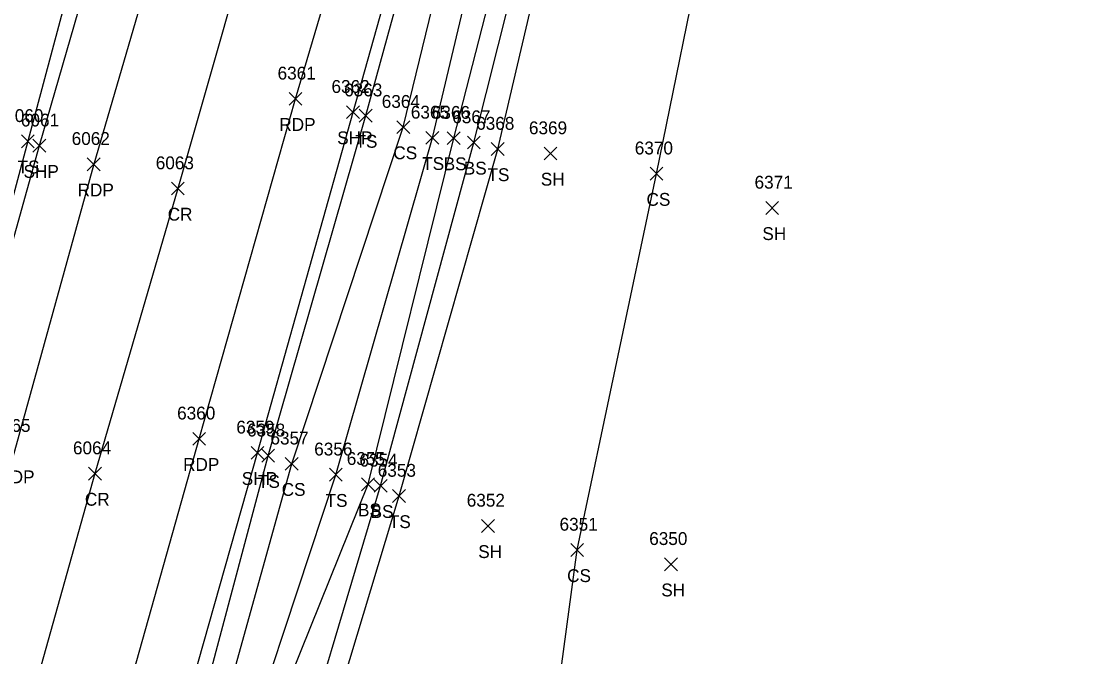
# Model space of a CAD drawing. Extents: x 1443912 to 1445411, y 621446 to 623693.
# Drawn here: x 1444530.8 to 1444695.3, y 621831 to 621930 of the extents above; entities that cross this region are included whole.
import ezdxf

# ---------------------------------------------------------------- set-up
doc = ezdxf.new("R2010")
doc.units = 0
for name, color, linetype in [('L_A', 7, 'Continuous'), ('L_I', 7, 'Continuous'), ('L_TIC', 7, 'Continuous'), ('LELB', 7, 'Continuous'), ('P_A', 7, 'Continuous'), ('P_I', 7, 'Continuous'), ('P_TIC', 7, 'Continuous'), ('PET', 7, 'Continuous'), ('PRC', 7, 'Continuous'), ('PSP', 7, 'Continuous')]:
    doc.layers.add(name, color=color, linetype=linetype)

msp = doc.modelspace()

# ---------------------------------------------------------------- linework, layer by layer
at = {"layer": 'L_TIC'}
for points in [[(1444583.53, 621914.31), (1444585.53, 621916.31)], [(1444585.53, 621914.31), (1444583.53, 621916.31)], [(1444589.39, 621912.52), (1444591.39, 621914.52)], [(1444591.39, 621912.52), (1444589.39, 621914.52)], [(1444530.89, 621910.31), (1444532.89, 621912.31)], [(1444532.89, 621910.31), (1444530.89, 621912.31)], [(1444593.92, 621910.85), (1444595.92, 621912.85)], [(1444595.92, 621910.85), (1444593.92, 621912.85)], [(1444597.24, 621910.81), (1444599.24, 621912.81)], [(1444599.24, 621910.81), (1444597.24, 621912.81)], [(1444600.37, 621910.13), (1444602.37, 621912.13)], [(1444602.37, 621910.13), (1444600.37, 621912.13)], [(1444604.09, 621909.11), (1444606.09, 621911.11)], [(1444606.09, 621909.11), (1444604.09, 621911.11)], [(1444612.32, 621908.41), (1444614.32, 621910.41)], [(1444614.32, 621908.41), (1444612.32, 621910.41)], [(1444628.84, 621905.27), (1444630.84, 621907.27)], [(1444630.84, 621905.27), (1444628.84, 621907.27)], [(1444646.85, 621899.94), (1444648.85, 621901.94)], [(1444648.85, 621899.94), (1444646.85, 621901.94)], [(1444568.34, 621861.36), (1444570.34, 621863.36)], [(1444570.34, 621861.36), (1444568.34, 621863.36)], [(1444572, 621860.11), (1444574, 621862.11)], [(1444574, 621860.11), (1444572, 621862.11)], [(1444578.87, 621858.4), (1444580.87, 621860.4)], [(1444580.87, 621858.4), (1444578.87, 621860.4)], [(1444583.89, 621856.92), (1444585.89, 621858.92)], [(1444585.89, 621856.92), (1444583.89, 621858.92)], [(1444585.86, 621856.67), (1444587.86, 621858.67)], [(1444587.86, 621856.67), (1444585.86, 621858.67)], [(1444588.72, 621855.09), (1444590.72, 621857.09)], [(1444590.72, 621855.09), (1444588.72, 621857.09)], [(1444602.58, 621850.43), (1444604.58, 621852.43)], [(1444604.58, 621850.43), (1444602.58, 621852.43)], [(1444616.47, 621846.69), (1444618.47, 621848.69)], [(1444618.47, 621846.69), (1444616.47, 621848.69)], [(1444631.1, 621844.46), (1444633.1, 621846.46)], [(1444633.1, 621844.46), (1444631.1, 621846.46)]]:
    msp.add_lwpolyline(points, dxfattribs=at)
at = {"layer": 'LELB'}
for points in [[(1444574.55, 622074.53), (1444566.78, 622059.21), (1444562.93, 622059.13), (1444561.5, 622033.21), (1444553.8, 621993.71), (1444545.42, 621962.05), (1444531.89, 621911.31), (1444519.55, 621865.32), (1444501.88, 621802.99), (1444488.02, 621753.84), (1444471.78, 621701.48), (1444460.31, 621656.88), (1444459.55, 621655.45), (1444452.09, 621632.21), (1444445.68, 621624.35), (1444438.52, 621621.89)], [(1444566.06, 621662.53), (1444540.75, 621668.47), (1444530.66, 621674.02), (1444525.23, 621679.72), (1444521.9, 621690.63), (1444527.67, 621715.46), (1444537.6, 621748.27), (1444544.57, 621771.14), (1444552.88, 621800.55), (1444569.34, 621862.36), (1444584.53, 621915.31), (1444599.33, 621969.16), (1444603.57, 621978.29), (1444612.14, 621984.45), (1444630.38, 621984.58), (1444648.65, 621983.32), (1444669.84, 621978.95)], [(1444562.11, 621788.81), (1444558.44, 621808.65), (1444573, 621861.11), (1444590.39, 621913.52), (1444603.53, 621967.44), (1444606.55, 621977.79), (1444612.68, 621980.77)], [(1444573.52, 621729.96), (1444606.82, 621757.8), (1444615.68, 621770.45), (1444599.05, 621772.87), (1444599.34, 621775.96), (1444583.66, 621779.46), (1444578.87, 621781.94), (1444577.18, 621792.61), (1444574.39, 621805.13), (1444589.72, 621856.09), (1444605.09, 621910.11), (1444615.08, 621952.69), (1444616.59, 621961.76), (1444617.15, 621962.73), (1444617.2, 621963.71), (1444617.35, 621964.73), (1444618.57, 621976.39)], [(1444596.93, 621775.31), (1444596.97, 621774.74), (1444581.99, 621775.15), (1444574.89, 621780.65), (1444572.86, 621790.77), (1444569.59, 621804.75), (1444563.93, 621805.88), (1444584.89, 621857.92), (1444598.24, 621911.81), (1444611.93, 621964.98), (1444612.45, 621975.13), (1444616.41, 621975.01)], [(1444596.93, 621775.31), (1444582.89, 621775.95), (1444576.67, 621781.14), (1444575.69, 621791.72), (1444571.4, 621805.9), (1444586.86, 621857.67), (1444601.37, 621911.13), (1444614.74, 621964.14), (1444616.41, 621975.01)], [(1444599.05, 621772.87), (1444581.28, 621773.15), (1444573.42, 621779.76), (1444571.45, 621790.67), (1444568.62, 621802.83), (1444561.95, 621805.21), (1444579.87, 621859.4), (1444594.92, 621911.85), (1444607.97, 621966.71)], [(1444615.68, 621770.45), (1444617.26, 621774.09), (1444611.19, 621801.02), (1444617.47, 621847.69), (1444629.84, 621906.27), (1444637.66, 621944.7), (1444644.37, 621956.1), (1444645.62, 621958.64)]]:
    msp.add_lwpolyline(points, dxfattribs=at)
at = {"layer": 'P_TIC'}
for points in [[(1444572.59, 621916.93), (1444574.59, 621918.93)], [(1444574.59, 621916.93), (1444572.59, 621918.93)], [(1444581.56, 621914.85), (1444583.56, 621916.85)], [(1444583.56, 621914.85), (1444581.56, 621916.85)], [(1444532.68, 621909.62), (1444534.68, 621911.62)], [(1444534.68, 621909.62), (1444532.68, 621911.62)], [(1444541.16, 621906.74), (1444543.16, 621908.74)], [(1444543.16, 621906.74), (1444541.16, 621908.74)], [(1444554.25, 621902.96), (1444556.25, 621904.96)], [(1444556.25, 621902.96), (1444554.25, 621904.96)], [(1444557.59, 621864), (1444559.59, 621866)], [(1444559.59, 621864), (1444557.59, 621866)], [(1444566.68, 621861.81), (1444568.68, 621863.81)], [(1444568.68, 621861.81), (1444566.68, 621863.81)], [(1444541.35, 621858.58), (1444543.35, 621860.58)], [(1444543.35, 621858.58), (1444541.35, 621860.58)]]:
    msp.add_lwpolyline(points, dxfattribs=at)
at = {"layer": 'PET'}
for points in [[(1444707.78, 622511.05), (1444700.03, 622482.58), (1444691.73, 622453.67), (1444679.73, 622411.23), (1444667.69, 622368.84), (1444653.08, 622317.67), (1444637.74, 622256.92), (1444626.42, 622209.58), (1444619.02, 622182.67), (1444605.37, 622130.08), (1444589.4, 622078.61), (1444578.44, 622026.86), (1444565.52, 621990.05), (1444556.87, 621958.17), (1444542.16, 621907.74), (1444529.8, 621863.07), (1444511.99, 621799.88), (1444498.16, 621751.76), (1444483.13, 621697.3), (1444470.84, 621653.16), (1444463.41, 621627.34), (1444449.07, 621575.52), (1444430.26, 621508.83), (1444421.17, 621471.46)], [(1444444.37, 621464.94), (1444461.94, 621522.87), (1444475.59, 621570.55), (1444487.99, 621616.26), (1444502.92, 621667.73), (1444516.83, 621718.16), (1444526.41, 621751.49), (1444537.28, 621789.32), (1444558.59, 621865), (1444573.59, 621917.93), (1444597.58, 621998.81), (1444610.14, 622044.19), (1444623.48, 622089.5), (1444632.2, 622118.09)]]:
    msp.add_lwpolyline(points, dxfattribs=at)
at = {"layer": 'PRC'}
msp.add_lwpolyline([(1444618.32, 622127.38), (1444604.97, 622075.74), (1444590.11, 622023.77), (1444578.57, 621985.29), (1444569.73, 621954.72), (1444555.25, 621903.96), (1444542.35, 621859.58), (1444524.46, 621796.02), (1444511.19, 621747.94), (1444495.68, 621693.61), (1444483.2, 621649.28), (1444475.93, 621623.97), (1444461.82, 621572.2), (1444443.22, 621505.41), (1444432.75, 621467.94)], dxfattribs=at)
at = {"layer": 'PSP'}
for points in [[(1444596.17, 622132.46), (1444585.6, 622096.58), (1444576.22, 622067.8), (1444567.15, 622029.85), (1444556.7, 621993.22), (1444548.18, 621960.88), (1444533.68, 621910.62), (1444520.92, 621865.12), (1444503.16, 621802.82), (1444490.06, 621753.65), (1444474.75, 621700.87), (1444461.97, 621656.27), (1444456.61, 621636.09), (1444438.52, 621570.3), (1444424.57, 621519.38), (1444411.29, 621473.11)], [(1444455.66, 621462.75), (1444472.05, 621519.48), (1444485.13, 621568.3), (1444497.88, 621612.67), (1444505.4, 621638.58), (1444519.01, 621689.59), (1444525.59, 621713.97), (1444535.94, 621748.74), (1444541.51, 621770.15), (1444550.94, 621803.78), (1444567.68, 621862.81), (1444582.56, 621915.85), (1444597.67, 621969.6), (1444608.45, 622008), (1444628.13, 622076.36), (1444639.3, 622115.36)]]:
    msp.add_lwpolyline(points, dxfattribs=at)

# ---------------------------------------------------------------- texts
at = {"layer": 'L_A'}
for s, p in [('TS', (1444582.93, 621910.31)), ('CS', (1444588.83, 621908.52)), ('TS', (1444593.33, 621906.85)), ('BS', (1444596.68, 621906.81)), ('TS', (1444530.3, 621906.31)), ('BS', (1444599.81, 621906.13)), ('TS', (1444603.5, 621905.11)), ('SH', (1444611.81, 621904.41)), ('CS', (1444628.28, 621901.27)), ('SH', (1444646.33, 621895.94)), ('TS', (1444567.75, 621857.36)), ('CS', (1444571.44, 621856.11)), ('TS', (1444578.28, 621854.4)), ('BS', (1444583.33, 621852.92)), ('BS', (1444585.3, 621852.67)), ('TS', (1444588.13, 621851.09)), ('SH', (1444602.06, 621846.43)), ('CS', (1444615.91, 621842.69)), ('SH', (1444630.58, 621840.46))]:
    msp.add_text(s, height=2, dxfattribs=at).set_placement(p)
at = {"layer": 'L_I'}
for s, p in [('6363', (1444581.17, 621918.31)), ('6364', (1444587.03, 621916.52)), ('6365', (1444591.56, 621914.85)), ('6366', (1444594.83, 621914.81)), ('6060', (1444528.37, 621914.31)), ('6367', (1444598.01, 621914.13)), ('6368', (1444601.74, 621913.11)), ('6369', (1444609.96, 621912.41)), ('6370', (1444626.45, 621909.27)), ('6371', (1444645.11, 621903.94)), ('6358', (1444566.04, 621865.36)), ('6357', (1444569.69, 621864.11)), ('6356', (1444576.51, 621862.4)), ('6355', (1444581.58, 621860.92)), ('6354', (1444583.55, 621860.67)), ('6353', (1444586.41, 621859.09)), ('6352', (1444600.27, 621854.43)), ('6351', (1444614.73, 621850.69)), ('6350', (1444628.7, 621848.46))]:
    msp.add_text(s, height=2, dxfattribs=at).set_placement(p)
at = {"layer": 'P_A'}
for s, p in [('RDP', (1444571.07, 621912.93)), ('SHP', (1444580.09, 621910.85)), ('SHP', (1444531.22, 621905.62)), ('RDP', (1444539.64, 621902.74)), ('CR', (1444553.68, 621898.96)), ('RDP', (1444556.08, 621860)), ('RDP', (1444527.29, 621858.07)), ('SHP', (1444565.22, 621857.81)), ('CR', (1444540.78, 621854.58))]:
    msp.add_text(s, height=2, dxfattribs=at).set_placement(p)
at = {"layer": 'P_I'}
for s, p in [('6361', (1444570.8, 621920.93)), ('6362', (1444579.2, 621918.85)), ('6061', (1444530.81, 621913.62)), ('6062', (1444538.72, 621910.74)), ('6063', (1444551.82, 621906.96)), ('6360', (1444555.15, 621868)), ('6065', (1444526.36, 621866.07)), ('6359', (1444564.37, 621865.81)), ('6064', (1444538.92, 621862.58))]:
    msp.add_text(s, height=2, dxfattribs=at).set_placement(p)

doc.saveas('drawing.dxf')
